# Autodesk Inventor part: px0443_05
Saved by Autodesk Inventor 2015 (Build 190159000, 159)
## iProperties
Created: 2019-05
Part Number: px0443_05
Checked By: TraceParts S.A.
Material: Generic
Catalog Web Link: www.traceparts.com
Document SubType Name: Modeling
Designer: TraceParts
Density: 1 g/cm^3
Appearance: Default
Company: TraceParts S.A.
Author: TraceParts
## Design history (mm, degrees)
feature "px0443_05.ipt"
body "Solid1"
